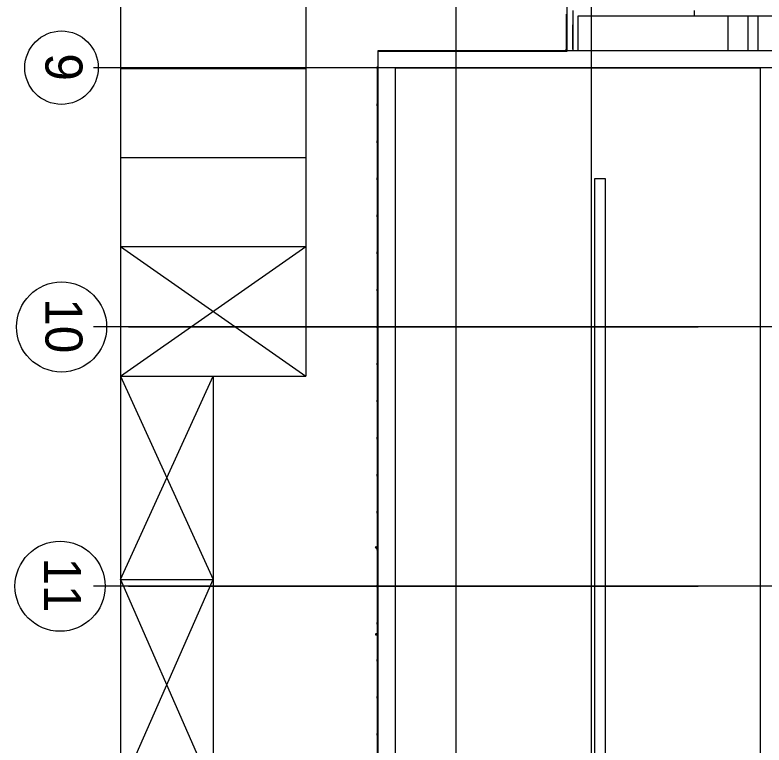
# Model space of a CAD drawing. Extents: x -264165 to -263575, y -1242333 to -1242036.
# Drawn here: x -263923.94 to -263903.73, y -1242151.17 to -1242131.46 of the extents above; entities that cross this region are included whole.
import ezdxf

# ---------------------------------------------------------------- set-up
doc = ezdxf.new("R2010")
doc.units = 0
doc.layers.add('KFA_HESCON_OSI_STAVBY', color=7, linetype='Continuous')
doc.layers.add('KFA_SITUACIA_DRS_VYTYCOVAK_SEDA', color=7, linetype='Continuous')

msp = doc.modelspace()

# ---------------------------------------------------------------- linework, layer by layer
at = {"layer": 'KFA_HESCON_OSI_STAVBY'}
for p, q in [((-263908.393, -1242080.447), (-263908.393, -1242248.737)), ((-263787.486, -1242132.882), (-263921.823, -1242132.882)), ((-263787.486, -1242139.882), (-263921.823, -1242139.882)), ((-263920.885, -1242139.882), (-263905.505, -1242139.882)), ((-263787.486, -1242146.882), (-263921.823, -1242146.882)), ((-263920.885, -1242146.882), (-263905.505, -1242146.882))]:
    msp.add_line(p, q, dxfattribs=at)
for centre, radius in [((-263922.688, -1242132.881), 0.991), ((-263922.688, -1242139.882), 1.216), ((-263922.728, -1242146.882), 1.216)]:
    msp.add_circle(centre, radius, dxfattribs=at)
at = {"layer": 'KFA_SITUACIA_DRS_VYTYCOVAK_SEDA'}
for p, q in [((-263921.093, -1242087.308), (-263921.093, -1242241.458)), ((-263916.093, -1242087.308), (-263916.093, -1242141.207)), ((-263912.043, -1242228.625), (-263912.043, -1242100.14)), ((-263909.043, -1242132.433), (-263909.043, -1242101.382)), ((-263908.893, -1242131.332), (-263908.893, -1242132.422)), ((-263908.893, -1242131.332), (-263908.893, -1242132.422)), ((-263905.608, -1242131.482), (-263905.608, -1242131.332)), ((-263905.608, -1242131.482), (-263905.608, -1242131.332)), ((-263909.068, -1242131.432), (-263909.068, -1242132.382)), ((-263909.068, -1242131.432), (-263909.068, -1242132.382)), ((-263908.743, -1242132.422), (-263908.743, -1242131.482)), ((-263908.743, -1242132.422), (-263908.743, -1242131.482)), ((-263908.743, -1242131.482), (-263905.608, -1242131.482)), ((-263908.743, -1242131.482), (-263905.608, -1242131.482)), ((-263905.608, -1242131.482), (-263901.768, -1242131.482)), ((-263905.608, -1242131.482), (-263901.768, -1242131.482)), ((-263904.701, -1242132.422), (-263904.701, -1242131.482)), ((-263904.701, -1242132.422), (-263904.701, -1242131.482)), ((-263904.168, -1242131.482), (-263904.168, -1242132.422)), ((-263904.168, -1242131.482), (-263904.168, -1242132.422)), ((-263903.901, -1242131.482), (-263903.901, -1242132.422)), ((-263903.901, -1242131.482), (-263903.901, -1242132.422)), ((-263908.893, -1242132.382), (-263908.893, -1242131.725)), ((-263908.893, -1242132.382), (-263908.893, -1242131.725)), ((-263914.153, -1242132.422), (-263914.153, -1242196.342)), ((-263914.153, -1242132.422), (-263914.153, -1242196.342)), ((-263903.358, -1242132.422), (-263914.153, -1242132.422)), ((-263903.358, -1242132.422), (-263914.153, -1242132.422)), ((-263914.143, -1242196.333), (-263914.143, -1242132.433)), ((-263914.143, -1242132.433), (-263909.043, -1242132.433)), ((-263909.068, -1242132.422), (-263909.068, -1242132.382)), ((-263909.068, -1242132.422), (-263909.068, -1242132.382)), ((-263908.893, -1242132.382), (-263908.893, -1242132.382)), ((-263908.893, -1242132.382), (-263908.893, -1242132.382)), ((-263908.893, -1242132.382), (-263908.893, -1242132.422)), ((-263908.893, -1242132.382), (-263908.893, -1242132.422)), ((-263908.893, -1242132.382), (-263908.893, -1242132.382)), ((-263908.893, -1242132.382), (-263908.893, -1242132.382)), ((-263921.093, -1242132.907), (-263916.093, -1242132.907)), ((-263914.168, -1242132.907), (-263914.168, -1242132.857)), ((-263914.168, -1242132.907), (-263914.168, -1242132.857)), ((-263914.168, -1242132.857), (-263914.153, -1242132.857)), ((-263914.168, -1242132.857), (-263914.153, -1242132.857)), ((-263914.168, -1242132.907), (-263914.168, -1242133.857)), ((-263914.168, -1242132.907), (-263914.168, -1242133.857)), ((-263914.168, -1242132.907), (-263914.168, -1242133.857)), ((-263914.168, -1242132.907), (-263914.168, -1242133.857)), ((-263913.683, -1242132.892), (-263913.683, -1242195.872)), ((-263913.683, -1242132.892), (-263913.683, -1242195.872)), ((-263903.828, -1242132.892), (-263913.683, -1242132.892)), ((-263903.828, -1242132.892), (-263913.683, -1242132.892)), ((-263903.828, -1242195.872), (-263903.828, -1242132.892)), ((-263903.828, -1242195.872), (-263903.828, -1242132.892)), ((-263914.168, -1242133.907), (-263914.168, -1242133.857)), ((-263914.168, -1242133.907), (-263914.168, -1242133.857)), ((-263914.168, -1242133.907), (-263914.168, -1242134.857)), ((-263914.168, -1242133.907), (-263914.168, -1242134.857)), ((-263914.168, -1242133.907), (-263914.168, -1242134.857)), ((-263914.168, -1242133.907), (-263914.168, -1242134.857)), ((-263914.168, -1242134.907), (-263914.168, -1242134.857)), ((-263914.168, -1242134.907), (-263914.168, -1242134.857)), ((-263914.168, -1242134.907), (-263914.168, -1242135.857)), ((-263914.168, -1242134.907), (-263914.168, -1242135.857)), ((-263914.168, -1242134.907), (-263914.168, -1242135.857)), ((-263914.168, -1242134.907), (-263914.168, -1242135.857)), ((-263921.093, -1242135.307), (-263916.093, -1242135.307)), ((-263914.168, -1242135.907), (-263914.168, -1242135.857)), ((-263914.168, -1242135.907), (-263914.168, -1242135.857)), ((-263914.168, -1242135.907), (-263914.168, -1242136.857)), ((-263914.168, -1242135.907), (-263914.168, -1242136.857)), ((-263914.168, -1242135.907), (-263914.168, -1242136.857)), ((-263914.168, -1242135.907), (-263914.168, -1242136.857)), ((-263908.308, -1242135.882), (-263908.308, -1242192.882)), ((-263908.308, -1242135.882), (-263908.308, -1242192.882)), ((-263908.008, -1242135.882), (-263908.308, -1242135.882)), ((-263908.008, -1242135.882), (-263908.308, -1242135.882)), ((-263908.008, -1242192.882), (-263908.008, -1242135.882)), ((-263908.008, -1242192.882), (-263908.008, -1242135.882)), ((-263914.168, -1242136.907), (-263914.168, -1242136.857)), ((-263914.168, -1242136.907), (-263914.168, -1242136.857)), ((-263914.168, -1242136.907), (-263914.168, -1242137.857)), ((-263914.168, -1242136.907), (-263914.168, -1242137.857)), ((-263914.168, -1242136.907), (-263914.168, -1242137.857)), ((-263914.168, -1242136.907), (-263914.168, -1242137.857)), ((-263921.093, -1242137.707), (-263916.093, -1242137.707)), ((-263921.093, -1242137.707), (-263916.093, -1242141.207)), ((-263921.093, -1242141.207), (-263916.093, -1242137.707)), ((-263914.168, -1242137.907), (-263914.168, -1242137.857)), ((-263914.168, -1242137.907), (-263914.168, -1242137.857)), ((-263914.168, -1242137.907), (-263914.168, -1242138.857)), ((-263914.168, -1242137.907), (-263914.168, -1242138.857)), ((-263914.168, -1242137.907), (-263914.168, -1242138.857)), ((-263914.168, -1242137.907), (-263914.168, -1242138.857)), ((-263914.168, -1242138.907), (-263914.168, -1242138.857)), ((-263914.168, -1242138.907), (-263914.168, -1242138.857)), ((-263914.168, -1242138.907), (-263914.168, -1242139.857)), ((-263914.168, -1242138.907), (-263914.168, -1242139.857)), ((-263914.168, -1242138.907), (-263914.168, -1242139.857)), ((-263914.168, -1242138.907), (-263914.168, -1242139.857)), ((-263914.168, -1242139.907), (-263914.168, -1242139.857)), ((-263914.168, -1242139.907), (-263914.168, -1242139.857)), ((-263914.168, -1242139.907), (-263914.168, -1242140.857)), ((-263914.168, -1242139.907), (-263914.168, -1242140.857)), ((-263914.168, -1242139.907), (-263914.168, -1242140.857)), ((-263914.168, -1242139.907), (-263914.168, -1242140.857)), ((-263914.168, -1242140.907), (-263914.168, -1242140.857)), ((-263914.168, -1242140.907), (-263914.168, -1242140.857)), ((-263914.168, -1242140.907), (-263914.168, -1242141.857)), ((-263914.168, -1242140.907), (-263914.168, -1242141.857)), ((-263914.168, -1242140.907), (-263914.168, -1242141.857)), ((-263914.168, -1242140.907), (-263914.168, -1242141.857)), ((-263921.093, -1242141.207), (-263916.093, -1242141.207)), ((-263921.093, -1242141.207), (-263918.593, -1242146.702)), ((-263921.093, -1242146.702), (-263918.593, -1242141.207)), ((-263918.593, -1242141.207), (-263918.593, -1242187.557)), ((-263914.168, -1242141.907), (-263914.168, -1242141.857)), ((-263914.168, -1242141.907), (-263914.168, -1242141.857)), ((-263914.168, -1242141.907), (-263914.168, -1242142.857)), ((-263914.168, -1242141.907), (-263914.168, -1242142.857)), ((-263914.168, -1242141.907), (-263914.168, -1242142.857)), ((-263914.168, -1242141.907), (-263914.168, -1242142.857)), ((-263914.168, -1242142.907), (-263914.168, -1242142.857)), ((-263914.168, -1242142.907), (-263914.168, -1242142.857)), ((-263914.168, -1242142.907), (-263914.168, -1242143.857)), ((-263914.168, -1242142.907), (-263914.168, -1242143.857)), ((-263914.168, -1242142.907), (-263914.168, -1242143.857)), ((-263914.168, -1242142.907), (-263914.168, -1242143.857)), ((-263914.168, -1242143.907), (-263914.168, -1242143.857)), ((-263914.168, -1242143.907), (-263914.168, -1242143.857)), ((-263914.168, -1242143.907), (-263914.168, -1242144.857)), ((-263914.168, -1242143.907), (-263914.168, -1242144.857)), ((-263914.168, -1242143.907), (-263914.168, -1242144.857)), ((-263914.168, -1242143.907), (-263914.168, -1242144.857)), ((-263914.168, -1242144.907), (-263914.168, -1242144.857)), ((-263914.168, -1242144.907), (-263914.168, -1242144.857)), ((-263914.168, -1242144.907), (-263914.168, -1242145.857)), ((-263914.168, -1242144.907), (-263914.168, -1242145.857)), ((-263914.213, -1242145.832), (-263914.21, -1242145.822)), ((-263914.213, -1242145.832), (-263914.21, -1242145.822)), ((-263914.21, -1242145.842), (-263914.213, -1242145.832)), ((-263914.21, -1242145.842), (-263914.213, -1242145.832)), ((-263914.21, -1242145.822), (-263914.203, -1242145.815)), ((-263914.21, -1242145.822), (-263914.203, -1242145.815)), ((-263914.21, -1242145.824), (-263914.21, -1242145.822)), ((-263914.21, -1242145.824), (-263914.21, -1242145.822)), ((-263914.21, -1242145.827), (-263914.21, -1242145.824)), ((-263914.21, -1242145.827), (-263914.21, -1242145.824)), ((-263914.21, -1242145.832), (-263914.21, -1242145.827)), ((-263914.21, -1242145.832), (-263914.21, -1242145.827)), ((-263914.21, -1242145.837), (-263914.21, -1242145.832)), ((-263914.21, -1242145.837), (-263914.21, -1242145.832)), ((-263914.21, -1242145.841), (-263914.21, -1242145.837)), ((-263914.21, -1242145.841), (-263914.21, -1242145.837)), ((-263914.21, -1242145.842), (-263914.21, -1242145.841)), ((-263914.21, -1242145.842), (-263914.21, -1242145.841)), ((-263914.203, -1242145.85), (-263914.21, -1242145.842)), ((-263914.203, -1242145.85), (-263914.21, -1242145.842)), ((-263914.203, -1242145.815), (-263914.193, -1242145.812)), ((-263914.203, -1242145.815), (-263914.193, -1242145.812)), ((-263914.203, -1242145.817), (-263914.203, -1242145.815)), ((-263914.203, -1242145.817), (-263914.203, -1242145.815)), ((-263914.203, -1242145.817), (-263914.193, -1242145.815)), ((-263914.203, -1242145.817), (-263914.193, -1242145.815)), ((-263914.203, -1242145.824), (-263914.203, -1242145.817)), ((-263914.203, -1242145.824), (-263914.203, -1242145.817)), ((-263914.203, -1242145.824), (-263914.193, -1242145.822)), ((-263914.203, -1242145.824), (-263914.193, -1242145.822)), ((-263914.203, -1242145.832), (-263914.203, -1242145.824)), ((-263914.203, -1242145.832), (-263914.203, -1242145.824)), ((-263914.203, -1242145.841), (-263914.203, -1242145.832)), ((-263914.203, -1242145.841), (-263914.203, -1242145.832)), ((-263914.203, -1242145.832), (-263914.193, -1242145.832)), ((-263914.203, -1242145.832), (-263914.193, -1242145.832)), ((-263914.203, -1242145.841), (-263914.193, -1242145.842)), ((-263914.203, -1242145.841), (-263914.193, -1242145.842)), ((-263914.203, -1242145.847), (-263914.203, -1242145.841)), ((-263914.203, -1242145.847), (-263914.203, -1242145.841)), ((-263914.203, -1242145.85), (-263914.203, -1242145.847)), ((-263914.203, -1242145.85), (-263914.203, -1242145.847)), ((-263914.203, -1242145.847), (-263914.193, -1242145.85)), ((-263914.203, -1242145.847), (-263914.193, -1242145.85)), ((-263914.193, -1242145.852), (-263914.203, -1242145.85)), ((-263914.193, -1242145.852), (-263914.203, -1242145.85)), ((-263914.193, -1242145.812), (-263914.183, -1242145.815)), ((-263914.193, -1242145.812), (-263914.183, -1242145.815)), ((-263914.193, -1242145.812), (-263914.193, -1242145.815)), ((-263914.193, -1242145.812), (-263914.193, -1242145.815)), ((-263914.193, -1242145.815), (-263914.183, -1242145.817)), ((-263914.193, -1242145.815), (-263914.183, -1242145.817)), ((-263914.193, -1242145.815), (-263914.193, -1242145.822)), ((-263914.193, -1242145.815), (-263914.193, -1242145.822)), ((-263914.193, -1242145.822), (-263914.193, -1242145.832)), ((-263914.193, -1242145.822), (-263914.193, -1242145.832)), ((-263914.193, -1242145.822), (-263914.183, -1242145.824)), ((-263914.193, -1242145.822), (-263914.183, -1242145.824)), ((-263914.193, -1242145.832), (-263914.193, -1242145.842)), ((-263914.193, -1242145.832), (-263914.193, -1242145.842)), ((-263914.193, -1242145.832), (-263914.183, -1242145.832)), ((-263914.193, -1242145.832), (-263914.183, -1242145.832)), ((-263914.193, -1242145.842), (-263914.183, -1242145.841)), ((-263914.193, -1242145.842), (-263914.183, -1242145.841)), ((-263914.193, -1242145.842), (-263914.193, -1242145.85)), ((-263914.193, -1242145.842), (-263914.193, -1242145.85)), ((-263914.193, -1242145.85), (-263914.183, -1242145.847)), ((-263914.193, -1242145.85), (-263914.183, -1242145.847)), ((-263914.193, -1242145.85), (-263914.193, -1242145.852)), ((-263914.193, -1242145.85), (-263914.193, -1242145.852)), ((-263914.183, -1242145.85), (-263914.193, -1242145.852)), ((-263914.183, -1242145.85), (-263914.193, -1242145.852)), ((-263914.183, -1242145.815), (-263914.176, -1242145.822)), ((-263914.183, -1242145.815), (-263914.176, -1242145.822)), ((-263914.183, -1242145.815), (-263914.183, -1242145.817)), ((-263914.183, -1242145.815), (-263914.183, -1242145.817)), ((-263914.183, -1242145.817), (-263914.183, -1242145.824)), ((-263914.183, -1242145.817), (-263914.183, -1242145.824)), ((-263914.183, -1242145.824), (-263914.183, -1242145.832)), ((-263914.183, -1242145.824), (-263914.183, -1242145.832)), ((-263914.183, -1242145.832), (-263914.183, -1242145.841)), ((-263914.183, -1242145.832), (-263914.183, -1242145.841)), ((-263914.183, -1242145.841), (-263914.183, -1242145.847)), ((-263914.183, -1242145.841), (-263914.183, -1242145.847)), ((-263914.176, -1242145.842), (-263914.183, -1242145.85)), ((-263914.176, -1242145.842), (-263914.183, -1242145.85)), ((-263914.183, -1242145.847), (-263914.183, -1242145.85)), ((-263914.183, -1242145.847), (-263914.183, -1242145.85)), ((-263914.176, -1242145.822), (-263914.168, -1242145.822)), ((-263914.176, -1242145.822), (-263914.168, -1242145.822)), ((-263914.176, -1242145.822), (-263914.176, -1242145.824)), ((-263914.176, -1242145.822), (-263914.176, -1242145.824)), ((-263914.176, -1242145.824), (-263914.168, -1242145.824)), ((-263914.176, -1242145.824), (-263914.168, -1242145.824)), ((-263914.176, -1242145.824), (-263914.176, -1242145.827)), ((-263914.176, -1242145.824), (-263914.176, -1242145.827)), ((-263914.176, -1242145.827), (-263914.168, -1242145.827)), ((-263914.176, -1242145.827), (-263914.168, -1242145.827)), ((-263914.176, -1242145.827), (-263914.176, -1242145.832)), ((-263914.176, -1242145.827), (-263914.176, -1242145.832)), ((-263914.176, -1242145.832), (-263914.168, -1242145.832)), ((-263914.176, -1242145.832), (-263914.168, -1242145.832)), ((-263914.176, -1242145.832), (-263914.176, -1242145.837)), ((-263914.176, -1242145.832), (-263914.176, -1242145.837)), ((-263914.176, -1242145.837), (-263914.168, -1242145.837)), ((-263914.176, -1242145.837), (-263914.168, -1242145.837)), ((-263914.176, -1242145.837), (-263914.176, -1242145.841)), ((-263914.176, -1242145.837), (-263914.176, -1242145.841)), ((-263914.176, -1242145.841), (-263914.168, -1242145.841)), ((-263914.176, -1242145.841), (-263914.168, -1242145.841)), ((-263914.176, -1242145.841), (-263914.176, -1242145.842)), ((-263914.176, -1242145.841), (-263914.176, -1242145.842)), ((-263914.176, -1242145.842), (-263914.168, -1242145.842)), ((-263914.176, -1242145.842), (-263914.168, -1242145.842)), ((-263914.168, -1242145.907), (-263914.168, -1242145.857)), ((-263914.168, -1242145.907), (-263914.168, -1242145.857)), ((-263914.168, -1242145.907), (-263914.168, -1242146.857)), ((-263914.168, -1242145.907), (-263914.168, -1242146.857)), ((-263921.093, -1242146.702), (-263918.593, -1242146.702)), ((-263921.093, -1242146.702), (-263918.611, -1242152.382)), ((-263921.093, -1242152.382), (-263918.593, -1242146.702)), ((-263914.168, -1242146.907), (-263914.168, -1242146.857)), ((-263914.168, -1242146.907), (-263914.168, -1242146.857)), ((-263914.168, -1242146.907), (-263914.168, -1242147.857)), ((-263914.168, -1242146.907), (-263914.168, -1242147.857)), ((-263914.168, -1242147.907), (-263914.168, -1242147.857)), ((-263914.168, -1242147.907), (-263914.168, -1242147.857)), ((-263914.168, -1242147.907), (-263914.168, -1242148.857)), ((-263914.168, -1242147.907), (-263914.168, -1242148.857)), ((-263914.213, -1242148.182), (-263914.21, -1242148.172)), ((-263914.213, -1242148.182), (-263914.21, -1242148.172)), ((-263914.21, -1242148.192), (-263914.213, -1242148.182)), ((-263914.21, -1242148.192), (-263914.213, -1242148.182)), ((-263914.21, -1242148.172), (-263914.203, -1242148.165)), ((-263914.21, -1242148.172), (-263914.203, -1242148.165)), ((-263914.21, -1242148.174), (-263914.21, -1242148.172)), ((-263914.21, -1242148.174), (-263914.21, -1242148.172)), ((-263914.21, -1242148.177), (-263914.21, -1242148.174)), ((-263914.21, -1242148.177), (-263914.21, -1242148.174)), ((-263914.21, -1242148.182), (-263914.21, -1242148.177)), ((-263914.21, -1242148.182), (-263914.21, -1242148.177)), ((-263914.21, -1242148.187), (-263914.21, -1242148.182)), ((-263914.21, -1242148.187), (-263914.21, -1242148.182)), ((-263914.21, -1242148.191), (-263914.21, -1242148.187)), ((-263914.21, -1242148.191), (-263914.21, -1242148.187)), ((-263914.21, -1242148.192), (-263914.21, -1242148.191)), ((-263914.21, -1242148.192), (-263914.21, -1242148.191)), ((-263914.203, -1242148.2), (-263914.21, -1242148.192)), ((-263914.203, -1242148.2), (-263914.21, -1242148.192)), ((-263914.203, -1242148.165), (-263914.193, -1242148.162)), ((-263914.203, -1242148.165), (-263914.193, -1242148.162)), ((-263914.203, -1242148.167), (-263914.203, -1242148.165)), ((-263914.203, -1242148.167), (-263914.203, -1242148.165)), ((-263914.193, -1242148.165), (-263914.203, -1242148.167)), ((-263914.193, -1242148.165), (-263914.203, -1242148.167)), ((-263914.203, -1242148.174), (-263914.203, -1242148.167)), ((-263914.203, -1242148.174), (-263914.203, -1242148.167)), ((-263914.193, -1242148.172), (-263914.203, -1242148.174)), ((-263914.193, -1242148.172), (-263914.203, -1242148.174)), ((-263914.203, -1242148.182), (-263914.203, -1242148.174)), ((-263914.203, -1242148.182), (-263914.203, -1242148.174)), ((-263914.203, -1242148.191), (-263914.203, -1242148.182)), ((-263914.203, -1242148.191), (-263914.203, -1242148.182)), ((-263914.193, -1242148.182), (-263914.203, -1242148.182)), ((-263914.193, -1242148.182), (-263914.203, -1242148.182)), ((-263914.203, -1242148.197), (-263914.203, -1242148.191)), ((-263914.203, -1242148.197), (-263914.203, -1242148.191)), ((-263914.193, -1242148.192), (-263914.203, -1242148.191)), ((-263914.193, -1242148.192), (-263914.203, -1242148.191)), ((-263914.193, -1242148.2), (-263914.203, -1242148.197)), ((-263914.193, -1242148.2), (-263914.203, -1242148.197)), ((-263914.203, -1242148.2), (-263914.203, -1242148.197)), ((-263914.203, -1242148.2), (-263914.203, -1242148.197)), ((-263914.193, -1242148.202), (-263914.203, -1242148.2)), ((-263914.193, -1242148.202), (-263914.203, -1242148.2)), ((-263914.193, -1242148.162), (-263914.193, -1242148.165)), ((-263914.193, -1242148.162), (-263914.193, -1242148.165)), ((-263914.193, -1242148.162), (-263914.183, -1242148.165)), ((-263914.193, -1242148.162), (-263914.183, -1242148.165)), ((-263914.193, -1242148.165), (-263914.193, -1242148.172)), ((-263914.193, -1242148.165), (-263914.193, -1242148.172)), ((-263914.183, -1242148.167), (-263914.193, -1242148.165)), ((-263914.183, -1242148.167), (-263914.193, -1242148.165)), ((-263914.193, -1242148.172), (-263914.193, -1242148.182)), ((-263914.193, -1242148.172), (-263914.193, -1242148.182)), ((-263914.183, -1242148.174), (-263914.193, -1242148.172)), ((-263914.183, -1242148.174), (-263914.193, -1242148.172)), ((-263914.193, -1242148.182), (-263914.193, -1242148.192)), ((-263914.193, -1242148.182), (-263914.193, -1242148.192)), ((-263914.183, -1242148.182), (-263914.193, -1242148.182)), ((-263914.183, -1242148.182), (-263914.193, -1242148.182)), ((-263914.183, -1242148.191), (-263914.193, -1242148.192)), ((-263914.183, -1242148.191), (-263914.193, -1242148.192)), ((-263914.193, -1242148.192), (-263914.193, -1242148.2)), ((-263914.193, -1242148.192), (-263914.193, -1242148.2)), ((-263914.183, -1242148.197), (-263914.193, -1242148.2)), ((-263914.183, -1242148.197), (-263914.193, -1242148.2)), ((-263914.193, -1242148.2), (-263914.193, -1242148.202)), ((-263914.193, -1242148.2), (-263914.193, -1242148.202)), ((-263914.183, -1242148.2), (-263914.193, -1242148.202)), ((-263914.183, -1242148.2), (-263914.193, -1242148.202)), ((-263914.183, -1242148.165), (-263914.183, -1242148.167)), ((-263914.183, -1242148.165), (-263914.183, -1242148.167)), ((-263914.183, -1242148.165), (-263914.176, -1242148.172)), ((-263914.183, -1242148.165), (-263914.176, -1242148.172)), ((-263914.183, -1242148.167), (-263914.183, -1242148.174)), ((-263914.183, -1242148.167), (-263914.183, -1242148.174)), ((-263914.183, -1242148.174), (-263914.183, -1242148.182)), ((-263914.183, -1242148.174), (-263914.183, -1242148.182)), ((-263914.183, -1242148.182), (-263914.183, -1242148.191)), ((-263914.183, -1242148.182), (-263914.183, -1242148.191)), ((-263914.183, -1242148.191), (-263914.183, -1242148.197)), ((-263914.183, -1242148.191), (-263914.183, -1242148.197)), ((-263914.176, -1242148.192), (-263914.183, -1242148.2)), ((-263914.176, -1242148.192), (-263914.183, -1242148.2)), ((-263914.183, -1242148.197), (-263914.183, -1242148.2)), ((-263914.183, -1242148.197), (-263914.183, -1242148.2)), ((-263914.168, -1242148.172), (-263914.176, -1242148.172)), ((-263914.168, -1242148.172), (-263914.176, -1242148.172)), ((-263914.176, -1242148.172), (-263914.176, -1242148.174)), ((-263914.176, -1242148.172), (-263914.176, -1242148.174)), ((-263914.168, -1242148.174), (-263914.176, -1242148.174)), ((-263914.168, -1242148.174), (-263914.176, -1242148.174)), ((-263914.176, -1242148.174), (-263914.176, -1242148.177)), ((-263914.176, -1242148.174), (-263914.176, -1242148.177)), ((-263914.168, -1242148.177), (-263914.176, -1242148.177)), ((-263914.168, -1242148.177), (-263914.176, -1242148.177)), ((-263914.176, -1242148.177), (-263914.176, -1242148.182)), ((-263914.176, -1242148.177), (-263914.176, -1242148.182)), ((-263914.168, -1242148.182), (-263914.176, -1242148.182)), ((-263914.168, -1242148.182), (-263914.176, -1242148.182)), ((-263914.176, -1242148.182), (-263914.176, -1242148.187)), ((-263914.176, -1242148.182), (-263914.176, -1242148.187)), ((-263914.168, -1242148.187), (-263914.176, -1242148.187)), ((-263914.168, -1242148.187), (-263914.176, -1242148.187)), ((-263914.176, -1242148.187), (-263914.176, -1242148.191)), ((-263914.176, -1242148.187), (-263914.176, -1242148.191)), ((-263914.168, -1242148.191), (-263914.176, -1242148.191)), ((-263914.168, -1242148.191), (-263914.176, -1242148.191)), ((-263914.176, -1242148.191), (-263914.176, -1242148.192)), ((-263914.176, -1242148.191), (-263914.176, -1242148.192)), ((-263914.168, -1242148.192), (-263914.176, -1242148.192)), ((-263914.168, -1242148.192), (-263914.176, -1242148.192)), ((-263914.168, -1242148.907), (-263914.168, -1242148.857)), ((-263914.168, -1242148.907), (-263914.168, -1242148.857)), ((-263914.168, -1242148.907), (-263914.168, -1242149.857)), ((-263914.168, -1242148.907), (-263914.168, -1242149.857)), ((-263914.168, -1242149.907), (-263914.168, -1242149.857)), ((-263914.168, -1242149.907), (-263914.168, -1242149.857)), ((-263914.168, -1242149.907), (-263914.168, -1242150.857)), ((-263914.168, -1242149.907), (-263914.168, -1242150.857)), ((-263914.168, -1242150.907), (-263914.168, -1242150.857)), ((-263914.168, -1242150.907), (-263914.168, -1242150.857)), ((-263914.168, -1242150.907), (-263914.168, -1242151.857)), ((-263914.168, -1242150.907), (-263914.168, -1242151.857))]:
    msp.add_line(p, q, dxfattribs=at)

# ---------------------------------------------------------------- texts
at = {"layer": 'KFA_HESCON_OSI_STAVBY'}
for s, p in [('9', (-263923.123, -1242132.493)), ('10', (-263923.123, -1242139.105)), ('11', (-263923.163, -1242146.105))]:
    msp.add_text(s, height=1, rotation=270, dxfattribs=at).set_placement(p)

doc.saveas('drawing.dxf')
